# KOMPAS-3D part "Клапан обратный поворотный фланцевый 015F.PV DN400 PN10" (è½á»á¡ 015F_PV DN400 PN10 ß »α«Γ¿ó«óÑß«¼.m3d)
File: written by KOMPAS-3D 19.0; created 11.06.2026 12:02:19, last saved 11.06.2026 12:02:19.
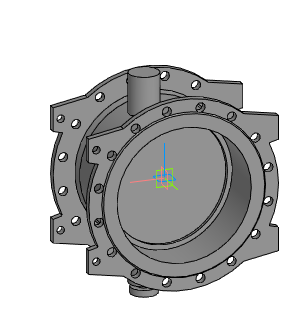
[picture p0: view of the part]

Document properties: Автор: Энергия; Полное имя файла: Z:\3.Личные\kachalov\001_3d для проектировщиков\5.5 Тип 015F.PV Клапан обратный поворотный с двумя эксцентриками\_stp_Клапан 015F.PV DN300-DN1200 с противовесом\Клапан 015F_PV DN400 PN10 с противовесом.m3d

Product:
- Part/product: Клапан обратный поворотный фланцевый 015F.PV DN400 PN10

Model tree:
1. Операция без истории:1
2. Сплайн:1
     Координата Y = 30; Координата Z = 200; Вес = 1; Координата X = 400; Координата Y = 82.661; Координата Z = 200; Вес = 0.333333; Координата X = 400; Координата Y = 82.661; Координата Z = -200; Вес = 0.333333; Координата Y = 30; Координата Z = -200; Вес = 1; Координата X = -400; Координата Y = -22.661; Координата Z = -200; Вес = 0.333333; Координата X = -400; Координата Y = -22.661; Координата Z = 200; Вес = 0.333333; Порядок = 4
